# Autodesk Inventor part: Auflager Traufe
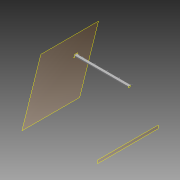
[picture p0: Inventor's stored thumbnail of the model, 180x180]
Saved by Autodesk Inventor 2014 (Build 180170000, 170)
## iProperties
Created: 2013-09
Part Number: Auflager Traufe
Material: Stahl
Document SubType Name: Modeling
Designer: Stefan Tammegger
Mass: 61419 g
Surface Area: 39157.8 cm^2
Volume: 7824.08 cm^3
Density: 7.85 g/cm^3
Appearance: Stahl
Author: Stefan Tammegger
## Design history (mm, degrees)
node "Blöcke"
  sketch "FR 160_80_4"
    geometry: L1 (-2916.646, 2613.194)-(-2844.646, 2613.194); L2 (-2840.646, 2609.194)-(-2840.646, 2457.194); L3 (-2844.646, 2453.194)-(-2916.646, 2453.194); L4 (-2920.646, 2457.194)-(-2920.646, 2609.194); L5 (-2844.646, 2609.194)-(-2916.646, 2609.194); L6 (-2916.646, 2609.194)-(-2916.646, 2457.194); L7 (-2916.646, 2457.194)-(-2844.646, 2457.194); L8 (-2844.646, 2457.194)-(-2844.646, 2609.194); A1 r 4 centre (-2916.646, 2609.194) between (-2916.646, 2613.194) and (-2920.646, 2609.194); A2 r 4 centre (-2844.646, 2609.194) between (-2840.646, 2609.194) and (-2844.646, 2613.194); A3 r 4 centre (-2916.646, 2457.194) between (-2920.646, 2457.194) and (-2916.646, 2453.194); A4 r 4 centre (-2844.646, 2457.194) between (-2844.646, 2453.194) and (-2840.646, 2457.194); 4 further points
    constraints: 16 end point, 8 point on circle, 8 tangent, 6 point on line, 4 centre point, 4 parallel, 3 equal radius, 2 perpendicular, 1 horizontal, 1 midpoint, 3 other
    dimensions: "d0" = 80 distance of point (-2840.646, 2453.194) point (-2920.646, 2453.194); "d1" = 160 distance of point (-2840.646, 2613.194) point (-2840.646, 2453.194); "d2" = 4 distance between parallel lines of L1 L5; "d3" = 4 radius of A1
workplane "Arbeitsebene1"
sketch "Skizze1"
  geometry: L1 (0, 30)-(-3300, 30) reference; L2 (0, 3800)-(0, -80) reference; 1 further point
  dimensions: "d4" = 2300 dimension on L1; "d5" = 3000 dimension on L2
  node "Referenz1"
  node "Referenz2"
  node "FR 160_80_4:1" dims "d4" = 2300, "d5" = 3000
workplane "Arbeitsebene2"
extrude "Extrusion1" new body sketch "Skizze1" stored distance "d6" = 10; taper "d7" = 0 deg
workplane "Arbeitsebene3"
feature "Trennen1"
workplane "Arbeitsebene4"
sketch "Skizze3"
  geometry: L1 (1537.072, 2486)-(1537.072, 2334) reference; L2 (1454.623, 2334)-(1454.623, 2486) reference; L3 (604.462, 2490)-(1532.949, 2490) reference; L4 (604.462, 2330)-(1532.949, 2330) reference; L5 (1605.847, 2500)-(1385.847, 2500); L6 (1385.847, 2500)-(1385.847, 2320); L7 (1385.847, 2320)-(1605.847, 2320); L8 (1605.847, 2320)-(1605.847, 2500); L9 (1454.623, 2410)-(1537.072, 2410); L10 (1495.847, 2410)-(1495.847, 2450.052); 1 further point
  constraints: 12 end point, 3 midpoint, 2 parallel, 2 perpendicular, 1 horizontal, 2 other
  dimensions: "d16" = 220 distance of L6.end L7.end; "d17" = 180 distance of L5.end L6.end
extrude "Extrusion2" new body sketch "Skizze3" distance "d18" = 10; taper "d19" = 0 deg
workplane "Arbeitsebene5"
feature "Trennen2"
sketch "Skizze4"
  geometry: L1 (1605.847, 2500)-(1385.847, 2500) reference; L2 (1385.847, 2500)-(1385.847, 2320) reference; L3 (1385.847, 2320)-(1605.847, 2320) reference; L4 (1605.847, 2320)-(1605.847, 2500) reference; L5 (1405.847, 2480)-(1585.847, 2480); L6 (1585.847, 2480)-(1585.847, 2340); L7 (1585.847, 2340)-(1405.847, 2340); L8 (1405.847, 2340)-(1405.847, 2480); 1 further point
  constraints: 8 end point, 3 other
  dimensions: "d21" = 20 distance between parallel lines of L4 L6
hole "Bohrung2" sketch "Skizze4" at (1405.847, 2480), (1585.847, 2480), (1585.847, 2340), (1405.847, 2340) diameter "d22" = 14; stored, may be unused: countersink angle "d26" = 90 deg, drill point angle "d28" = 118 deg; dims "d23" = 6, "d24" = 4, "d25" = 2, "d27" = 8
sketch "Skizze5"
  geometry: L1 (-80, 0)-(-80, 152) reference; L2 (-4, -4)-(-76, -4) reference; L3 (2903.869, 517.087)-(-413.46, 226.858) reference; L4 (2912.584, 417.467)-(-404.744, 127.239) reference; L5 (-80, 246)-(0, 246); L6 (0, 246)-(0, -4); L7 (0, -4)-(-80, -4); L8 (-80, -4)-(-80, 246); 1 further point
  constraints: 8 end point, 2 collinear, 2 parallel, 1 horizontal, 1 perpendicular
  dimensions: "d29" = 80 distance of L6.end L7.end; "d30" = 250 distance of L7.end L5.start
extrude "Extrusion3" new body sketch "Skizze5" distance "d31" = 8; taper "d32" = 0 deg
sketch "Skizze6"
  geometry: L1 (0, 246)-(-80, 246) reference; L2 (-80, 246)-(-80, -4) reference; 2 further points
  dimensions: "d33" = 40 distance from line of L2 point (-40, 211); "d34" = 35 distance from line of L1 point (-40, 211)
hole "Bohrung3" sketch "Skizze6" at (-40, 211) diameter "d35" = 14; stored, may be unused: countersink angle "d39" = 90 deg, drill point angle "d41" = 118 deg; dims "d36" = 6, "d37" = 4, "d38" = 2, "d40" = 14
sketch "Skizze7"
  geometry: L1 (3827.659, 0)-(0, 0) reference; L2 (135.167, -462.209)-(-695.676, 2894.036) reference; L3 (-637.434, 2908.454)-(193.408, -447.791) reference; L4 (14.218, -6.922)-(21.984, -5); L5 (21.984, -5)-(36.402, -63.242); L6 (36.402, -63.242)-(28.636, -65.164); L7 (28.636, -65.164)-(14.218, -6.922); 1 further point
  constraints: 8 end point, 2 parallel, 1 collinear, 1 perpendicular
  dimensions: "d42" = 8 distance of L5.end L6.end; "d43" = 60 distance of L4.end L5.end; "d44" = 5 distance from line of L4.end L1
extrude "Extrusion4" new body sketch "Skizze7" distance "d45" = 90; taper "d46" = 0 deg
sketch "Skizze8"
  geometry: L1 (-60, 90)-(0, 90) reference; L2 (-60, 0)-(-60, 90) reference; 2 further points
  dimensions: "d47" = 35 distance from line of point (-20, 55) L1; "d48" = 40 distance from line of L2 point (-20, 55)
hole "Bohrung4" sketch "Skizze8" at (-20, 55) diameter "d49" = 10.106; stored, may be unused: countersink angle "d53" = 90 deg, drill point angle "d55" = 118 deg; dims "d50" = 10, "d51" = 4, "d52" = 2, "d54" = 14
sketch "Skizze9"
  geometry: L1 (21.984, -5)-(14.218, -6.922) reference; L2 (14.218, -6.922)-(28.636, -65.164) reference; L3 (135.167, -462.209)-(-695.676, 2894.036) reference; L4 (28.636, -65.164)-(36.402, -63.242) reference; L5 (84.271, -6.922)-(92.036, -5); L6 (92.036, -5)-(106.454, -63.242); L7 (106.454, -63.242)-(98.689, -65.164); L8 (98.689, -65.164)-(84.271, -6.922); L9 (-637.434, 2908.454)-(193.408, -447.791) reference; 1 further point
  constraints: 8 end point, 2 parallel, 1 collinear, 1 horizontal alignment, 1 perpendicular
  dimensions: "d56" = 8 distance of L6.end L7.end; "d57" = 60 distance of L5.end L6.end
extrude "Extrusion5" new body sketch "Skizze9" distance "d58" = 90; taper "d59" = 0 deg
sketch "Skizze11"
  geometry: L1 (3827.659, 4)-(-0.997, 4) reference; L2 (3827.659, -76)-(18.949, -76) reference; L3 (3759.659, -6)-(3767.659, -6); L4 (3767.659, -6)-(3767.659, -66); L5 (3767.659, -66)-(3759.659, -66); L6 (3759.659, -66)-(3759.659, -6); L7 (3767.659, -409.111)-(3767.659, 2908.217) reference; 1 further point
  constraints: 8 end point, 2 parallel, 1 collinear, 1 horizontal, 1 perpendicular
  dimensions: "d69" = 8 distance of L4.end L5.end; "d70" = 60 distance of L3.end L4.end; "d71" = 10 distance between parallel lines of L3 L1
extrude "Extrusion6" new body sketch "Skizze11" distance "d72" = 90; taper "d73" = 0 deg
sketch "Skizze12"
  geometry: C1 r 7 at (30, 55) reference; 1 further point
hole "Bohrung6" sketch "Skizze12" at (30, 55) diameter "d74" = 14; stored, may be unused: countersink angle "d78" = 90 deg, drill point angle "d80" = 118 deg; dims "d75" = 6, "d76" = 4, "d77" = 2, "d79" = 14
sketch "Skizze13"
  geometry: L1 (2977.659, -6)-(2985.659, -6); L2 (2985.659, -6)-(2985.659, -66); L3 (2985.659, -66)-(2977.659, -66); L4 (2977.659, -66)-(2977.659, -6); L5 (3827.659, 4)-(-0.997, 4) reference; L6 (2977.659, 2908.217)-(2977.659, -409.111) reference; L7 (2917.659, -409.111)-(2917.659, 2908.217) reference; L8 (2909.659, -6)-(2917.659, -6); L9 (2917.659, -6)-(2917.659, -66); L10 (2917.659, -66)-(2909.659, -66); L11 (2909.659, -66)-(2909.659, -6); 1 further point
  constraints: 16 end point, 4 parallel, 3 collinear, 2 horizontal, 2 perpendicular
  dimensions: "d81" = 8 distance of L2.end L3.end; "d82" = 60 distance of L1.end L2.end; "d83" = 10 distance between parallel lines of L5 L1; "d84" = 8 distance of L9.end L10.end; "d85" = 60 distance of L8.end L9.end
extrude "Extrusion7" new body sketch "Skizze13" distance "d86" = 90; taper "d87" = 0 deg
pattern_linear "Rechteckige Anordnung1" dims "d97" = 850
sketch "Skizze15"
  geometry: C1 r 5.053 at (-23.167, 55) reference; 1 further point
hole "Bohrung8" sketch "Skizze15" at (-23.167, 55) diameter "d98" = 14; stored, may be unused: countersink angle "d102" = 90 deg, drill point angle "d104" = 118 deg; dims "d99" = 6, "d100" = 4, "d101" = 2, "d103" = 14
sketch "Skizze16"
  geometry: C1 r 7 at (3735.659, 56) reference; C2 r 7 at (3735.659, 16) reference; 1 further point
hole "Bohrung9" sketch "Skizze16" at (3735.659, 56), (3735.659, 16) diameter "d105" = 10.106; stored, may be unused: countersink angle "d109" = 90 deg, drill point angle "d111" = 118 deg; dims "d106" = 6, "d107" = 4, "d108" = 2, "d110" = 14
sketch "Skizze18"
  geometry: C1 r 7 at (30, 55) reference; 1 further point
hole "Bohrung11" sketch "Skizze18" at (30, 55) diameter "d119" = 14; stored, may be unused: countersink angle "d123" = 90 deg, drill point angle "d125" = 118 deg; dims "d120" = 6, "d121" = 4, "d122" = 2, "d124" = 14
node "Volumenkörper1"
node "Volumenkörper2"
node "Referenz5"
node "Referenz6"
node "Volumenkörper3"
node "Referenz7"
node "Referenz8"
node "Volumenkörper4"
node "Referenz9"
node "Referenz10"
node "Volumenkörper5"
node "Volumenkörper6"
node "Referenz12"
node "Referenz13"
node "Referenz14"
node "Volumenkörper7"
node "Referenz16"
node "Referenz17"
node "Referenz18"
node "Referenz20"
other parameters: "d15" = -418, "d20" = 0
